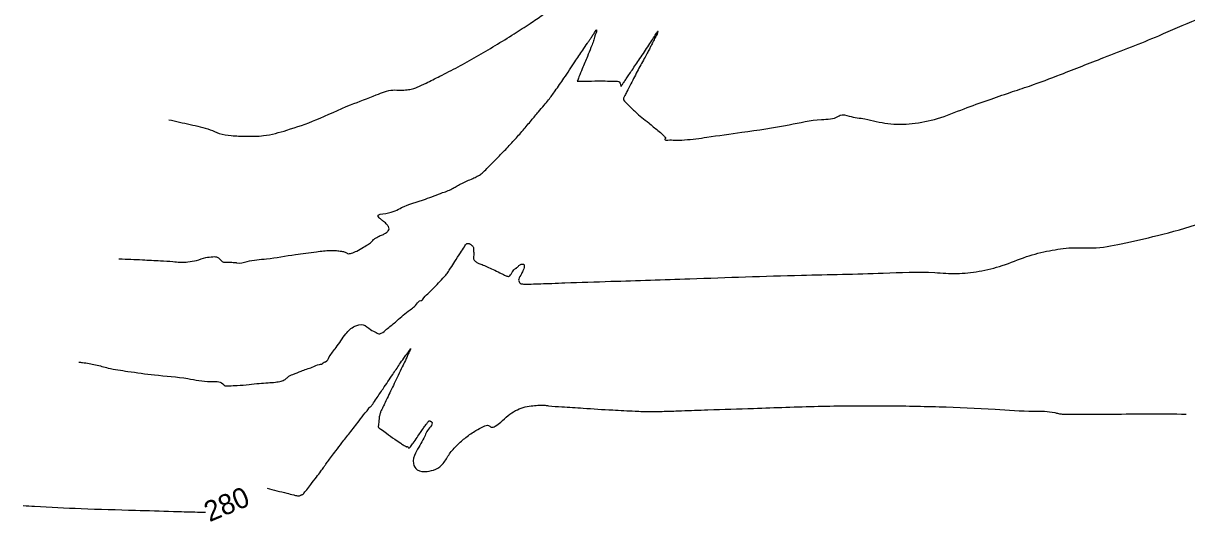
# Model space of a CAD drawing. Extents: x -475575 to -473225, y -1116053 to -1114104.
# Drawn here: x -475560.7 to -475332.2, y -1115427.3 to -1115329.3 of the extents above; entities that cross this region are included whole.
import ezdxf

# ---------------------------------------------------------------- set-up
doc = ezdxf.new("R2010")
doc.units = 0
for name, color, linetype in [('Vrstevnice_hlavni', 7, 'Continuous'), ('Vrstevnice_popis', 7, 'Continuous'), ('Vrstevnice_vedlejsi', 7, 'Continuous')]:
    doc.layers.add(name, color=color, linetype=linetype)

msp = doc.modelspace()

# ---------------------------------------------------------------- linework, layer by layer
at = {"layer": 'Vrstevnice_hlavni'}
for points in [[(-475512.80000000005, -1115420.717), (-475508.91000000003, -1115421.691), (-475507.565, -1115422.024), (-475506.821, -1115422.202), (-475506.677, -1115422.226), (-475506.505, -1115422.2070000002), (-475506.304, -1115422.144), (-475506.074, -1115422.038), (-475505.908, -1115421.966), (-475505.80600000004, -1115421.929), (-475505.76800000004, -1115421.9270000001), (-475505.7, -1115421.871), (-475505.60400000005, -1115421.762), (-475505.478, -1115421.6), (-475505.015, -1115421.003), (-475504.215, -1115419.972), (-475503.07700000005, -1115418.506), (-475502.22000000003, -1115417.3760000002), (-475501.64300000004, -1115416.584), (-475501.347, -1115416.128), (-475500.85500000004, -1115415.435), (-475500.168, -1115414.503), (-475499.28500000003, -1115413.334), (-475498.085, -1115411.774), (-475496.568, -1115409.823), (-475494.733, -1115407.483), (-475493.5, -1115405.9000000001), (-475492.867, -1115405.0760000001), (-475492.835, -1115405.009), (-475492.804, -1115404.9540000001), (-475492.775, -1115404.909), (-475492.748, -1115404.874), (-475492.69100000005, -1115404.827), (-475492.606, -1115404.767), (-475492.49100000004, -1115404.693), (-475492.36000000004, -1115404.571), (-475492.211, -1115404.399), (-475492.047, -1115404.1770000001), (-475491.309, -1115403.0960000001), (-475489.998, -1115401.154), (-475488.114, -1115398.3530000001), (-475486.76300000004, -1115396.357), (-475485.946, -1115395.165), (-475485.661, -1115394.7780000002), (-475485.36600000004, -1115394.36), (-475485.06, -1115393.912), (-475484.744, -1115393.432), (-475484.59500000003, -1115393.247), (-475484.614, -1115393.355), (-475484.80000000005, -1115393.756), (-475484.972, -1115394.1330000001), (-475485.128, -1115394.485), (-475485.26900000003, -1115394.8120000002), (-475485.635, -1115395.595), (-475486.226, -1115396.834), (-475487.042, -1115398.5280000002), (-475487.80700000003, -1115400.121), (-475488.521, -1115401.6130000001), (-475489.183, -1115403.002), (-475489.72000000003, -1115404.122), (-475490.134, -1115404.973), (-475490.423, -1115405.554), (-475490.634, -1115406.174), (-475490.76800000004, -1115406.8320000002), (-475490.824, -1115407.53), (-475490.875, -1115408.056), (-475490.92000000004, -1115408.412), (-475490.961, -1115408.597), (-475490.44, -1115409.1), (-475489.359, -1115409.921), (-475487.717, -1115411.061), (-475486.549, -1115411.862), (-475485.85400000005, -1115412.325), (-475485.63300000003, -1115412.45), (-475485.465, -1115412.522), (-475485.35000000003, -1115412.5420000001), (-475485.28900000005, -1115412.509), (-475485.206, -1115412.543), (-475485.09900000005, -1115412.644), (-475484.97000000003, -1115412.811), (-475484.63200000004, -1115412.549), (-475484.08400000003, -1115411.858), (-475483.32800000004, -1115410.737), (-475482.663, -1115409.764), (-475482.08900000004, -1115408.9370000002), (-475481.607, -1115408.2580000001), (-475481.265, -1115407.789), (-475481.063, -1115407.529), (-475481.00100000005, -1115407.479), (-475480.927, -1115407.459), (-475480.841, -1115407.468), (-475480.743, -1115407.5080000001), (-475480.651, -1115407.561), (-475480.563, -1115407.628), (-475480.48000000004, -1115407.708), (-475480.423, -1115407.772), (-475480.391, -1115407.8190000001)], [(-475480.391, -1115407.8190000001), (-475480.385, -1115407.8490000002), (-475480.92100000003, -1115408.8560000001), (-475481.998, -1115410.84), (-475483.617, -1115413.801), (-475484.053, -1115415.8800000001), (-475483.30600000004, -1115417.077), (-475481.37600000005, -1115417.391), (-475479.67500000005, -1115416.976), (-475478.204, -1115415.83), (-475476.962, -1115413.9540000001), (-475475.473, -1115412.252), (-475473.739, -1115410.726), (-475471.75800000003, -1115409.374), (-475470.27400000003, -1115408.588), (-475469.288, -1115408.367), (-475468.799, -1115408.713), (-475467.998, -1115408.5050000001), (-475466.884, -1115407.743), (-475465.45800000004, -1115406.429), (-475463.992, -1115405.4570000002), (-475462.48600000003, -1115404.828), (-475460.939, -1115404.5420000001), (-475459.591, -1115404.392), (-475458.44, -1115404.378), (-475457.488, -1115404.5), (-475454.91500000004, -1115404.699), (-475450.721, -1115404.976), (-475444.906, -1115405.33), (-475440.506, -1115405.556), (-475437.522, -1115405.654), (-475435.95300000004, -1115405.6230000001), (-475434.412, -1115405.583), (-475432.9, -1115405.534), (-475431.417, -1115405.476), (-475426.193, -1115405.3020000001), (-475417.22900000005, -1115405.011), (-475404.52400000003, -1115404.605), (-475392.381, -1115404.4980000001), (-475380.799, -1115404.692), (-475369.77900000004, -1115405.1870000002), (-475362.199, -1115405.573), (-475358.06, -1115405.852), (-475357.36000000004, -1115406.023), (-475356.60000000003, -1115406.1300000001), (-475355.777, -1115406.173), (-475354.89300000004, -1115406.152), (-475351.88700000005, -1115406.138), (-475346.759, -1115406.129), (-475332.25700000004, -1115406.125)], [(-475560.68141554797, -1115424.1121804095), (-475558.455, -1115424.2510000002), (-475549.331, -1115424.6970000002), (-475538.661, -1115425.0250000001), (-475531.20300000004, -1115425.252), (-475526.955, -1115425.377), (-475524.88, -1115425.423)]]:
    msp.add_spline(points, degree=3, dxfattribs=at)
at = {"layer": 'Vrstevnice_vedlejsi'}
msp.add_line((-475541.89792202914, -1115375.6166153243), (-475541.81700000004, -1115375.6300000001), dxfattribs=at)
for points in [[(-475449.08400000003, -1115340.699), (-475446.357, -1115340.6600000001), (-475444.506, -1115340.7310000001), (-475443.531, -1115340.912), (-475443.433, -1115341.2010000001), (-475443.36600000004, -1115341.4340000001), (-475443.32800000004, -1115341.611), (-475443.321, -1115341.7310000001), (-475443.20900000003, -1115341.651), (-475442.993, -1115341.371), (-475442.67100000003, -1115340.8900000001), (-475442.248, -1115340.257), (-475441.722, -1115339.472), (-475441.096, -1115338.5350000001), (-475440.37600000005, -1115337.466), (-475439.564, -1115336.266), (-475438.65900000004, -1115334.9340000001), (-475437.815, -1115333.663), (-475437.032, -1115332.452), (-475436.309, -1115331.303), (-475435.99100000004, -1115330.87), (-475436.076, -1115331.1530000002), (-475436.565, -1115332.152), (-475436.99700000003, -1115333.027), (-475437.37100000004, -1115333.776), (-475437.689, -1115334.401), (-475438.131, -1115335.235), (-475438.69700000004, -1115336.2780000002), (-475439.38800000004, -1115337.531), (-475440.09, -1115338.837), (-475440.802, -1115340.196), (-475441.526, -1115341.608), (-475442.097, -1115342.727), (-475442.51700000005, -1115343.553), (-475442.78400000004, -1115344.087), (-475442.092, -1115345.159), (-475440.44100000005, -1115346.7680000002), (-475437.831, -1115348.916), (-475436.02900000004, -1115350.416), (-475435.036, -1115351.2680000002), (-475434.852, -1115351.4740000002), (-475434.711, -1115351.631), (-475434.613, -1115351.7410000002), (-475434.558, -1115351.803), (-475434.549, -1115351.898), (-475434.585, -1115352.027), (-475434.668, -1115352.19), (-475434.06600000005, -1115352.2820000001), (-475432.77900000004, -1115352.303), (-475430.808, -1115352.254), (-475426.391, -1115351.735), (-475419.527, -1115350.747), (-475410.21800000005, -1115349.29), (-475403.896, -1115348.249), (-475400.56200000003, -1115347.625), (-475400.215, -1115347.416), (-475398.481, -1115347.587), (-475395.36100000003, -1115348.137), (-475390.85500000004, -1115349.066), (-475386.106, -1115349.043), (-475381.11600000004, -1115348.067), (-475375.884, -1115346.139), (-475371.129, -1115344.431), (-475366.851, -1115342.943), (-475363.05000000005, -1115341.674), (-475356.917, -1115339.391), (-475348.45200000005, -1115336.094), (-475337.656, -1115331.783), (-475330.17100000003, -1115328.629), (-475325.998, -1115326.634), (-475325.13700000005, -1115325.796), (-475323.036, -1115324.149), (-475319.696, -1115321.692), (-475315.117, -1115318.4270000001), (-475311.87700000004, -1115315.541), (-475309.977, -1115313.033), (-475309.416, -1115310.904), (-475308.95, -1115308.794), (-475308.579, -1115306.703), (-475308.303, -1115304.632), (-475307.57700000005, -1115300.689), (-475306.40400000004, -1115294.875), (-475304.781, -1115287.189), (-475303.842, -1115278.622), (-475303.58400000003, -1115269.173), (-475304.01, -1115258.843), (-475304.15400000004, -1115250.848), (-475304.01700000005, -1115245.191), (-475303.59900000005, -1115241.869), (-475303.53500000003, -1115239.087), (-475303.826, -1115236.845), (-475304.472, -1115235.1430000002), (-475305.206, -1115231.7780000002), (-475306.02800000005, -1115226.749), (-475306.938, -1115220.056), (-475308.049, -1115214.467), (-475309.36000000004, -1115209.98)], [(-475472.23500000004, -1115374.306), (-475472.19800000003, -1115374.299), (-475472.188, -1115374.496), (-475472.206, -1115374.897), (-475472.25200000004, -1115375.503), (-475471.99600000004, -1115376.0150000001), (-475471.438, -1115376.431), (-475470.57700000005, -1115376.753), (-475469.564, -1115377.185), (-475468.39800000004, -1115377.727), (-475467.079, -1115378.378), (-475466.135, -1115378.824), (-475465.56600000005, -1115379.063), (-475465.373, -1115379.0960000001), (-475465.14, -1115378.956), (-475464.869, -1115378.6430000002), (-475464.559, -1115378.1570000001), (-475464.29500000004, -1115377.804), (-475464.07700000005, -1115377.585), (-475463.905, -1115377.4980000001), (-475463.721, -1115377.367), (-475463.52400000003, -1115377.193), (-475463.315, -1115376.9740000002), (-475463.109, -1115376.813), (-475462.906, -1115376.7110000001), (-475462.706, -1115376.666), (-475462.548, -1115376.661), (-475462.43200000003, -1115376.695), (-475462.357, -1115376.769), (-475462.30700000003, -1115376.899), (-475462.282, -1115377.084), (-475462.281, -1115377.3260000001), (-475462.46, -1115377.828), (-475462.821, -1115378.591), (-475463.362, -1115379.615), (-475463.22400000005, -1115380.287), (-475462.405, -1115380.609), (-475460.907, -1115380.5790000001), (-475459.053, -1115380.526), (-475456.84500000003, -1115380.45), (-475454.282, -1115380.35), (-475445.25700000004, -1115380.049), (-475429.76800000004, -1115379.547), (-475407.81700000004, -1115378.844), (-475391.766, -1115378.439), (-475381.61500000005, -1115378.3320000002), (-475377.364, -1115378.523), (-475372.951, -1115378.064), (-475368.375, -1115376.955), (-475363.63700000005, -1115375.1970000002), (-475359.09900000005, -1115374.034), (-475354.759, -1115373.466), (-475350.619, -1115373.493), (-475345.005, -1115372.689), (-475337.917, -1115371.054), (-475329.35500000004, -1115368.588), (-475322.005, -1115365.301), (-475315.86600000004, -1115361.1940000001), (-475310.939, -1115356.267), (-475306.26700000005, -1115351.887), (-475301.851, -1115348.0550000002), (-475297.69100000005, -1115344.771), (-475294.19800000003, -1115340.674), (-475291.37100000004, -1115335.766), (-475289.212, -1115330.046), (-475287.57700000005, -1115325.864), (-475286.467, -1115323.222), (-475285.881, -1115322.118), (-475284.97900000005, -1115320.249), (-475283.76200000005, -1115317.6160000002), (-475282.228, -1115314.219), (-475281.124, -1115311.276), (-475280.44800000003, -1115308.787), (-475280.201, -1115306.753), (-475279.98600000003, -1115303.651), (-475279.802, -1115299.482), (-475279.651, -1115294.245), (-475279.53900000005, -1115290.5590000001), (-475279.466, -1115288.425), (-475279.43200000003, -1115287.842), (-475279.39400000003, -1115287.2070000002), (-475279.352, -1115286.519), (-475279.30600000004, -1115285.779), (-475279.42500000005, -1115284.328), (-475279.71, -1115282.163), (-475280.16000000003, -1115279.287), (-475280.78900000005, -1115274.178), (-475281.597, -1115266.837), (-475282.58300000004, -1115257.264), (-475283.33900000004, -1115250.2480000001), (-475283.86500000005, -1115245.79), (-475284.16000000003, -1115243.889), (-475284.629, -1115241.72), (-475285.27, -1115239.283), (-475286.08300000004, -1115236.577), (-475286.63, -1115234.767), (-475286.91000000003, -1115233.851)], [(-475467.981, -1115333.7310000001), (-475464.254, -1115331.399), (-475461.14400000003, -1115329.385), (-475458.65, -1115327.688), (-475456.77400000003, -1115326.307), (-475455.397, -1115325.3390000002), (-475454.52, -1115324.7820000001), (-475454.14400000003, -1115324.638), (-475453.797, -1115324.397), (-475453.481, -1115324.06), (-475453.195, -1115323.6260000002), (-475452.74700000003, -1115323.146), (-475452.134, -1115322.619), (-475451.359, -1115322.044), (-475450.829, -1115321.652), (-475450.543, -1115321.441), (-475450.503, -1115321.412), (-475450.416, -1115321.185), (-475450.283, -1115320.762), (-475450.103, -1115320.142), (-475449.592, -1115319.348), (-475448.748, -1115318.381), (-475447.571, -1115317.24), (-475446.21, -1115315.808), (-475444.663, -1115314.083), (-475442.93100000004, -1115312.067), (-475441.63, -1115310.638), (-475440.761, -1115309.7950000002), (-475440.324, -1115309.539), (-475439.836, -1115309.272), (-475439.30000000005, -1115308.993), (-475438.71300000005, -1115308.702), (-475438.28900000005, -1115308.406), (-475438.027, -1115308.104), (-475437.92600000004, -1115307.796), (-475437.42500000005, -1115307.161), (-475436.52300000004, -1115306.199), (-475435.22000000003, -1115304.909), (-475434.25800000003, -1115303.9910000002), (-475433.63700000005, -1115303.4440000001), (-475433.356, -1115303.2680000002), (-475433.161, -1115303.146), (-475433.054, -1115303.078), (-475433.033, -1115303.064), (-475433.01, -1115303.047), (-475432.987, -1115303.027), (-475432.96300000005, -1115303.003), (-475432.53, -1115302.35), (-475431.688, -1115301.067), (-475430.43600000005, -1115299.154), (-475429.462, -1115297.685), (-475428.765, -1115296.661), (-475428.34500000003, -1115296.08), (-475428.12600000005, -1115295.8190000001), (-475428.108, -1115295.877), (-475428.293, -1115296.254), (-475428.59900000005, -1115296.9030000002), (-475429.027, -1115297.823), (-475429.57700000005, -1115299.0150000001), (-475429.97500000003, -1115299.882), (-475430.221, -1115300.423), (-475430.315, -1115300.639), (-475430.55500000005, -1115301.136), (-475430.939, -1115301.913), (-475431.46900000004, -1115302.972), (-475431.869, -1115303.691), (-475432.139, -1115304.07), (-475432.28, -1115304.11), (-475432.408, -1115304.122), (-475432.522, -1115304.107), (-475432.623, -1115304.066), (-475432.712, -1115304.142), (-475432.787, -1115304.338), (-475432.85000000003, -1115304.652), (-475432.90400000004, -1115304.9570000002), (-475432.94800000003, -1115305.254), (-475432.983, -1115305.543), (-475433.00100000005, -1115305.921), (-475433.003, -1115306.3900000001), (-475432.988, -1115306.949), (-475432.532, -1115307.5280000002), (-475431.636, -1115308.1260000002), (-475430.298, -1115308.744), (-475429.11600000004, -1115309.2380000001), (-475428.08900000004, -1115309.607), (-475427.21900000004, -1115309.851), (-475426.625, -1115310.027), (-475426.309, -1115310.136), (-475426.26900000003, -1115310.1770000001), (-475426.20800000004, -1115310.247), (-475426.12600000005, -1115310.3460000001), (-475426.022, -1115310.4740000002), (-475425.7, -1115310.631), (-475425.161, -1115310.82), (-475424.40400000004, -1115311.038), (-475423.897, -1115311.188), (-475423.641, -1115311.269)], [(-475541.81700000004, -1115375.6300000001), (-475537.25800000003, -1115375.821), (-475533.74700000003, -1115375.9980000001), (-475531.28500000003, -1115376.1600000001), (-475529.87200000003, -1115376.308), (-475528.325, -1115376.2310000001), (-475526.64400000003, -1115375.929), (-475524.829, -1115375.401), (-475523.444, -1115375.21), (-475522.489, -1115375.354), (-475521.965, -1115375.834), (-475521.58900000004, -1115376.148), (-475521.36000000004, -1115376.296), (-475521.28, -1115376.277), (-475520.978, -1115376.274), (-475520.455, -1115376.287), (-475519.71, -1115376.316), (-475519.17000000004, -1115376.3490000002), (-475518.83400000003, -1115376.385), (-475518.70300000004, -1115376.424), (-475516.726, -1115376.168), (-475512.906, -1115375.619), (-475507.24000000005, -1115374.776), (-475503.06100000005, -1115374.2280000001), (-475500.367, -1115373.975), (-475499.158, -1115374.0180000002), (-475498.189, -1115374.135), (-475497.45800000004, -1115374.327), (-475496.966, -1115374.593), (-475496.19700000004, -1115374.5180000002), (-475495.15300000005, -1115374.102), (-475493.832, -1115373.345), (-475492.84300000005, -1115372.718), (-475492.18700000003, -1115372.223), (-475491.864, -1115371.858), (-475491.384, -1115371.502), (-475490.74600000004, -1115371.156), (-475489.95, -1115370.818), (-475489.364, -1115370.469), (-475488.987, -1115370.111), (-475488.819, -1115369.742), (-475488.95200000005, -1115369.288), (-475489.385, -1115368.749), (-475490.119, -1115368.124), (-475490.629, -1115367.676), (-475490.91500000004, -1115367.406), (-475490.976, -1115367.3120000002), (-475489.45800000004, -1115366.696), (-475486.36100000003, -1115365.558), (-475481.684, -1115363.897), (-475478.30500000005, -1115362.6300000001), (-475476.223, -1115361.757), (-475475.439, -1115361.2780000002), (-475474.537, -1115360.799), (-475473.51700000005, -1115360.318), (-475472.38, -1115359.837), (-475471.505, -1115359.4200000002), (-475470.891, -1115359.067), (-475470.54000000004, -1115358.7780000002), (-475469.634, -1115357.899), (-475468.174, -1115356.429), (-475466.16000000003, -1115354.369), (-475464.27, -1115352.343), (-475462.506, -1115350.352), (-475460.867, -1115348.396), (-475459.48600000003, -1115346.749), (-475458.363, -1115345.412), (-475457.498, -1115344.3830000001), (-475456.20300000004, -1115342.6230000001), (-475454.478, -1115340.1300000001), (-475452.32200000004, -1115336.906), (-475450.783, -1115334.612), (-475449.86100000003, -1115333.25), (-475449.55600000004, -1115332.8190000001), (-475449.196, -1115332.2850000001), (-475448.782, -1115331.649), (-475448.313, -1115330.911), (-475448.074, -1115330.639), (-475448.06700000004, -1115330.8360000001), (-475448.28900000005, -1115331.5), (-475448.47900000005, -1115332.087), (-475448.635, -1115332.597), (-475448.75800000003, -1115333.03), (-475449.172, -1115334.1230000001), (-475449.87600000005, -1115335.875), (-475450.87, -1115338.286), (-475451.53500000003, -1115339.898), (-475451.87, -1115340.712), (-475451.875, -1115340.726), (-475451.874, -1115340.735), (-475451.867, -1115340.739), (-475451.85400000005, -1115340.7380000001), (-475451.842, -1115340.737), (-475451.831, -1115340.737), (-475451.821, -1115340.737), (-475450.906, -1115340.7240000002), (-475449.08400000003, -1115340.699)], [(-475532.0710680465, -1115348.2875923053), (-475527.89400000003, -1115349.23), (-475523.987, -1115350.2580000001), (-475522.19, -1115350.973), (-475519.83800000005, -1115351.405), (-475516.93200000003, -1115351.554), (-475513.472, -1115351.419), (-475508.89200000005, -1115350.344), (-475503.194, -1115348.33), (-475496.37700000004, -1115345.3760000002), (-475491.337, -1115343.419), (-475488.07300000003, -1115342.4570000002), (-475486.585, -1115342.492), (-475485.299, -1115342.413), (-475484.216, -1115342.2210000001), (-475483.33400000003, -1115341.915), (-475481.553, -1115341.094), (-475478.87100000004, -1115339.76), (-475475.28900000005, -1115337.911), (-475471.65900000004, -1115335.901), (-475467.981, -1115333.7310000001)], [(-475549.7580473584, -1115395.9100298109), (-475549.07300000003, -1115396), (-475546.471, -1115396.458), (-475543.99100000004, -1115397.0860000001), (-475540.145, -1115397.745), (-475534.93200000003, -1115398.436), (-475528.353, -1115399.158), (-475523.873, -1115399.736), (-475521.493, -1115400.1700000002), (-475521.21400000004, -1115400.459), (-475520.261, -1115400.578), (-475518.636, -1115400.5250000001), (-475516.33900000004, -1115400.301), (-475514.32700000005, -1115400.117), (-475512.601, -1115399.972), (-475511.161, -1115399.867), (-475510.038, -1115399.651), (-475509.233, -1115399.325), (-475508.74600000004, -1115398.888), (-475507.70300000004, -1115398.341), (-475506.103, -1115397.6840000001), (-475503.94800000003, -1115396.9170000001), (-475502.49600000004, -1115396.388), (-475501.749, -1115396.0990000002), (-475501.705, -1115396.049), (-475501.62, -1115395.992), (-475501.492, -1115395.928), (-475501.321, -1115395.858), (-475500.571, -1115394.9100000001), (-475499.24100000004, -1115393.0820000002), (-475497.33, -1115390.3760000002), (-475495.56200000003, -1115388.882), (-475493.934, -1115388.601), (-475492.44800000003, -1115389.531), (-475491.356, -1115390.1160000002), (-475490.658, -1115390.3560000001), (-475490.353, -1115390.2510000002), (-475489.324, -1115389.4810000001), (-475487.57, -1115388.046), (-475485.092, -1115385.945), (-475483.43100000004, -1115384.546), (-475482.587, -1115383.847), (-475482.56100000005, -1115383.848), (-475482.01700000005, -1115383.315), (-475480.956, -1115382.247), (-475479.378, -1115380.644), (-475478.24000000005, -1115379.4510000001), (-475477.54000000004, -1115378.669), (-475477.27900000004, -1115378.296), (-475476.737, -1115377.4640000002), (-475475.913, -1115376.174), (-475474.808, -1115374.426), (-475474.026, -1115373.246), (-475473.565, -1115372.636), (-475473.427, -1115372.595), (-475473.275, -1115372.5960000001), (-475473.109, -1115372.637), (-475472.93000000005, -1115372.72), (-475472.75, -1115372.8390000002), (-475472.569, -1115372.994), (-475472.38700000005, -1115373.186), (-475472.27300000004, -1115373.4170000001), (-475472.228, -1115373.689), (-475472.25100000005, -1115374.002), (-475472.253, -1115374.2070000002), (-475472.23500000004, -1115374.306)]]:
    msp.add_spline(points, degree=3, dxfattribs=at)

# ---------------------------------------------------------------- texts
at = {"layer": 'Vrstevnice_popis'}
msp.add_text(' 280 ', height=3.9999999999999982, rotation=22.768389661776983, dxfattribs=at).set_placement((-475525.4609368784, -1115427.9719697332))

doc.saveas('drawing.dxf')
